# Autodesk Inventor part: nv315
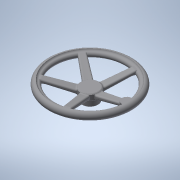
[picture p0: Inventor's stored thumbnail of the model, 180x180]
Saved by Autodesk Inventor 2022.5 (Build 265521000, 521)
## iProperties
Created: 2016-12
Part Number: nv315
Material: 一般
Document SubType Name: Modeling
Designer: imaocorp
Density: 1 g/cm^3
Appearance: 既定
Author: imaocorp
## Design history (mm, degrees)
node "nv315.x_t1"
node "nv315"
node "Base1"
